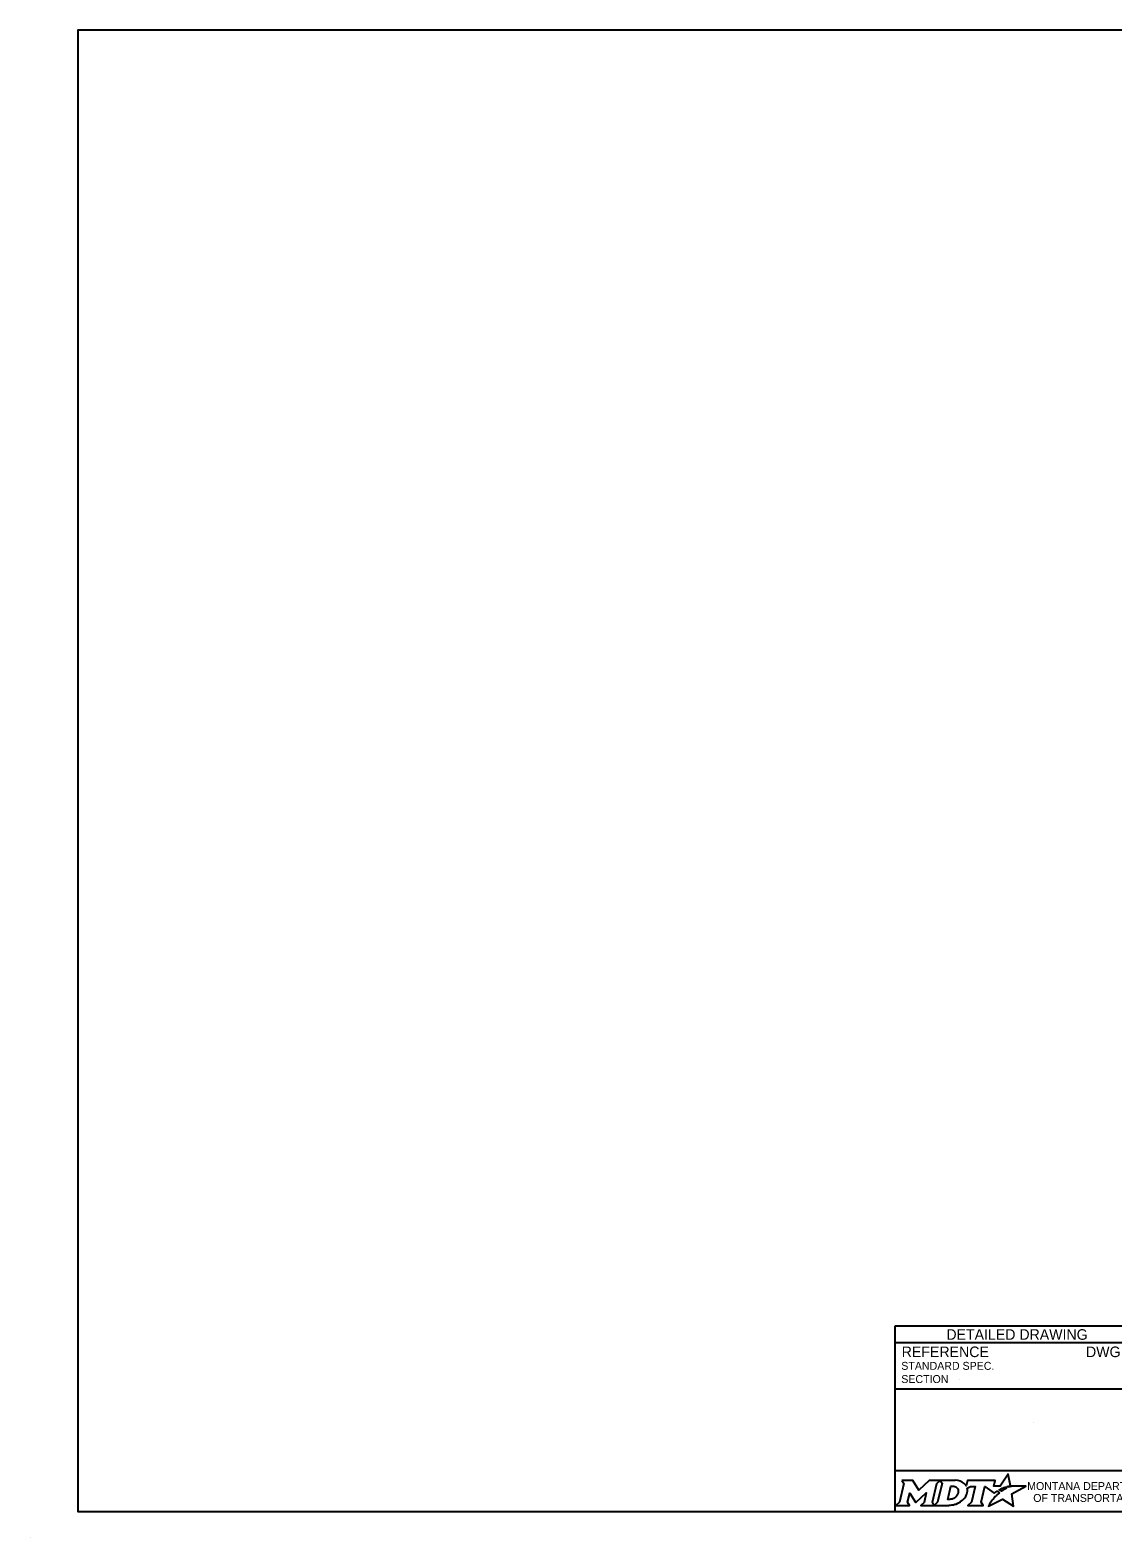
# Model space of a CAD drawing. Extents: x 49991.4 to 50021, y 49987.6 to 50011.4.
# Drawn here: x 49999.98 to 50008.17, y 49999.86 to 50011.26 of the extents above; entities that cross this region are included whole.
import ezdxf

# ---------------------------------------------------------------- set-up
doc = ezdxf.new("R2010")
doc.units = 0
doc.layers.add('Level 1', color=7, linetype='Continuous')
doc.layers.add('Level 2', color=7, linetype='Continuous')

msp = doc.modelspace()

# ---------------------------------------------------------------- linework, layer by layer
at = {"layer": 'Level 1'}
msp.add_line((49999.977, 49999.862), (49999.977, 49999.862), dxfattribs=at)
msp.add_lwpolyline([(50008.615, 50011.263), (50000.336, 50011.263), (50000.336, 50000.062), (50008.615, 50000.062)], close=True, dxfattribs=at)
at = {"layer": 'Level 2'}
for p, q in [((50008.615, 50001.462), (50006.515, 50001.462)), ((50006.515, 50001.462), (50006.515, 50000.062)), ((50008.615, 50001.337), (50006.515, 50001.337)), ((50007.009, 50001.063), (50007.009, 50001.063)), ((50008.615, 50000.987), (50006.515, 50000.987)), ((50007.565, 50000.738), (50007.565, 50000.738)), ((50008.615, 50000.369), (50006.515, 50000.369))]:
    msp.add_line(p, q, dxfattribs=at)
for points in [[(50007.377, 50000.245), (50007.367, 50000.25), (50007.378, 50000.253), (50007.39, 50000.255), (50007.373, 50000.345), (50007.313, 50000.254), (50007.266, 50000.253), (50007.276, 50000.297), (50007.067, 50000.297), (50007.057, 50000.255), (50007.051, 50000.263)], [(50006.57, 50000.297), (50006.584, 50000.274), (50006.551, 50000.131), (50006.525, 50000.108), (50006.627, 50000.108), (50006.613, 50000.131), (50006.629, 50000.201), (50006.673, 50000.132), (50006.678, 50000.132), (50006.753, 50000.202), (50006.737, 50000.13), (50006.712, 50000.108), (50006.814, 50000.108), (50006.8, 50000.132), (50006.833, 50000.274)], [(50006.833, 50000.274), (50006.859, 50000.297), (50006.776, 50000.297), (50006.697, 50000.224), (50006.652, 50000.297), (50006.57, 50000.297)], [(50006.972, 50000.297), (50006.859, 50000.297), (50006.873, 50000.275), (50006.839, 50000.131), (50006.814, 50000.108), (50006.925, 50000.108)], [(50006.996, 50000.211), (50006.995, 50000.203), (50006.992, 50000.193), (50006.988, 50000.185), (50006.982, 50000.178), (50006.976, 50000.171), (50006.968, 50000.164), (50006.959, 50000.16), (50006.95, 50000.156), (50006.941, 50000.154), (50006.932, 50000.153), (50006.916, 50000.153), (50006.94, 50000.253), (50006.956, 50000.253), (50006.963, 50000.252), (50006.971, 50000.25), (50006.977, 50000.247), (50006.983, 50000.243), (50006.988, 50000.238), (50006.992, 50000.232), (50006.995, 50000.226), (50006.996, 50000.218), (50006.996, 50000.215), (50006.996, 50000.211)], [(50007.064, 50000.238), (50007.088, 50000.251), (50007.125, 50000.251), (50007.097, 50000.131), (50007.069, 50000.108), (50007.185, 50000.108), (50007.168, 50000.131), (50007.196, 50000.251), (50007.268, 50000.2), (50007.289, 50000.215), (50007.309, 50000.204)], [(50007.253, 50000.148), (50007.237, 50000.124), (50007.233, 50000.116), (50007.227, 50000.107), (50007.225, 50000.103), (50007.33, 50000.156), (50007.414, 50000.101), (50007.401, 50000.194), (50007.508, 50000.252), (50007.458, 50000.253), (50007.428, 50000.253), (50007.407, 50000.254), (50007.401, 50000.252), (50007.396, 50000.251), (50007.387, 50000.249), (50007.377, 50000.245)], [(50007.327, 50000.217), (50007.324, 50000.215), (50007.306, 50000.225), (50007.316, 50000.231), (50007.32, 50000.233), (50007.329, 50000.237), (50007.335, 50000.239), (50007.343, 50000.243), (50007.35, 50000.245), (50007.362, 50000.238), (50007.358, 50000.236), (50007.353, 50000.233), (50007.349, 50000.231), (50007.344, 50000.228), (50007.342, 50000.227), (50007.339, 50000.225), (50007.337, 50000.224), (50007.334, 50000.222), (50007.332, 50000.221), (50007.329, 50000.219), (50007.327, 50000.217)], [(50006.97, 50000.116), (50006.979, 50000.118), (50006.992, 50000.124), (50007.012, 50000.135)], [(50007.267, 50000.164), (50007.267, 50000.164)]]:
    msp.add_lwpolyline(points, dxfattribs=at)
for centre, radius, start, end in [((50006.995, 50000.219), 0.0709, 339.5329, 15.8582), ((50006.951, 50000.236), 0.118, 300.9103, 339.1383)]:
    msp.add_arc(centre, radius, start, end, dxfattribs=at)
for centre, major_axis, ratio, start_param, end_param in [((50006.97, 50000.25), (0.0834, -0.0037), 0.568097, 0.61298, 1.570796), ((50007.026, 50000.257), (0.0361, -0.0295), 0.469099, 1.225588, 1.570796), ((50006.925, 50000.257), (0, 0.148), 0.987302, 3.139398, 3.456847), ((50007.26, 50000.156), (-0.00694, -0.00806), 0.008222, 0, 3.137361), ((50007.276, 50000.174), (-0.0098, -0.0102), 0.016458, 3.141593, 6.279097), ((50007.297, 50000.194), (-0.0112, -0.0097), 0.021651, 3.157348, 6.283185)]:
    msp.add_ellipse(centre, major_axis=major_axis, ratio=ratio, start_param=start_param, end_param=end_param, dxfattribs=at)

# ---------------------------------------------------------------- texts
for s, height, p in [('DETAILED DRAWING', 0.0799, (50006.906, 50001.36)), ('REFERENCE', 0.08, (50006.568, 50001.229)), ('DWG. NO.', 0.08, (50007.962, 50001.229)), ('STANDARD SPEC.', 0.06, (50006.565, 50001.133)), ('SECTION', 0.06, (50006.565, 50001.033))]:
    msp.add_text(s, height=height, dxfattribs=at).set_placement(p)
for s, p in [('MONTANA DEPARTMENT', (50007.517, 50000.224)), ('OF TRANSPORTATION', (50007.563, 50000.134))]:
    msp.add_text(s, height=0.06, rotation=360, dxfattribs=at).set_placement(p)

doc.saveas('drawing.dxf')
